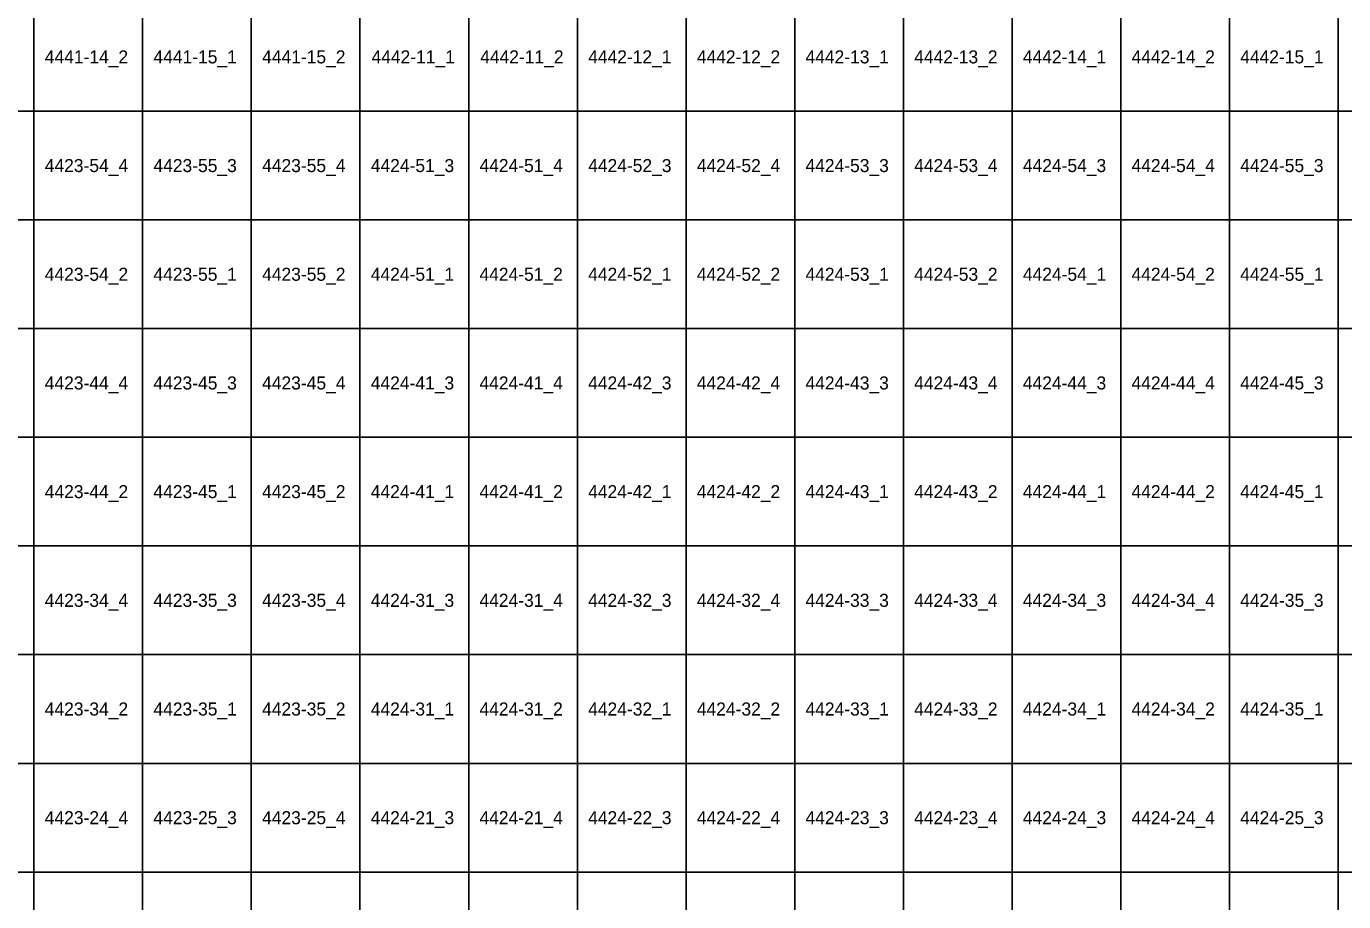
# Model space of a CAD drawing. Extents: x 312500 to 765000, y 172500 to 440000.
# Drawn here: x 667325 to 697629, y 331819 to 351952 of the extents above; entities that cross this region are included whole.
import ezdxf

# ---------------------------------------------------------------- set-up
doc = ezdxf.new("R2010")
doc.units = 0
doc.layers.add('Topo5_ramis_TKS2025', color=7, linetype='Continuous')
doc.layers.add('Topo5_ramis_TKS2025_Nr', color=7, linetype='Continuous')

msp = doc.modelspace()

# ---------------------------------------------------------------- linework, layer by layer
at = {"layer": 'Topo5_ramis_TKS2025'}
for points in [[(665000, 350000), (665000, 352500), (667500, 352500), (667500, 350000), (665000, 350000)], [(667500, 350000), (667500, 352500), (670000, 352500), (670000, 350000), (667500, 350000)], [(670000, 350000), (670000, 352500), (672500, 352500), (672500, 350000), (670000, 350000)], [(672500, 350000), (672500, 352500), (675000, 352500), (675000, 350000), (672500, 350000)], [(675000, 350000), (675000, 352500), (677500, 352500), (677500, 350000), (675000, 350000)], [(677500, 350000), (677500, 352500), (680000, 352500), (680000, 350000), (677500, 350000)], [(680000, 350000), (680000, 352500), (682500, 352500), (682500, 350000), (680000, 350000)], [(682500, 350000), (682500, 352500), (685000, 352500), (685000, 350000), (682500, 350000)], [(685000, 350000), (685000, 352500), (687500, 352500), (687500, 350000), (685000, 350000)], [(687500, 350000), (687500, 352500), (690000, 352500), (690000, 350000), (687500, 350000)], [(690000, 350000), (690000, 352500), (692500, 352500), (692500, 350000), (690000, 350000)], [(692500, 350000), (692500, 352500), (695000, 352500), (695000, 350000), (692500, 350000)], [(695000, 350000), (695000, 352500), (697500, 352500), (697500, 350000), (695000, 350000)], [(697500, 350000), (697500, 352500), (700000, 352500), (700000, 350000), (697500, 350000)], [(665000, 347500), (665000, 350000), (667500, 350000), (667500, 347500), (665000, 347500)], [(667500, 347500), (667500, 350000), (670000, 350000), (670000, 347500), (667500, 347500)], [(670000, 347500), (670000, 350000), (672500, 350000), (672500, 347500), (670000, 347500)], [(672500, 347500), (672500, 350000), (675000, 350000), (675000, 347500), (672500, 347500)], [(675000, 347500), (675000, 350000), (677500, 350000), (677500, 347500), (675000, 347500)], [(677500, 347500), (677500, 350000), (680000, 350000), (680000, 347500), (677500, 347500)], [(680000, 347500), (680000, 350000), (682500, 350000), (682500, 347500), (680000, 347500)], [(682500, 347500), (682500, 350000), (685000, 350000), (685000, 347500), (682500, 347500)], [(685000, 347500), (685000, 350000), (687500, 350000), (687500, 347500), (685000, 347500)], [(687500, 347500), (687500, 350000), (690000, 350000), (690000, 347500), (687500, 347500)], [(690000, 347500), (690000, 350000), (692500, 350000), (692500, 347500), (690000, 347500)], [(692500, 347500), (692500, 350000), (695000, 350000), (695000, 347500), (692500, 347500)], [(695000, 347500), (695000, 350000), (697500, 350000), (697500, 347500), (695000, 347500)], [(697500, 347500), (697500, 350000), (700000, 350000), (700000, 347500), (697500, 347500)], [(665000, 345000), (665000, 347500), (667500, 347500), (667500, 345000), (665000, 345000)], [(667500, 345000), (667500, 347500), (670000, 347500), (670000, 345000), (667500, 345000)], [(670000, 345000), (670000, 347500), (672500, 347500), (672500, 345000), (670000, 345000)], [(672500, 345000), (672500, 347500), (675000, 347500), (675000, 345000), (672500, 345000)], [(675000, 345000), (675000, 347500), (677500, 347500), (677500, 345000), (675000, 345000)], [(677500, 345000), (677500, 347500), (680000, 347500), (680000, 345000), (677500, 345000)], [(680000, 345000), (680000, 347500), (682500, 347500), (682500, 345000), (680000, 345000)], [(682500, 345000), (682500, 347500), (685000, 347500), (685000, 345000), (682500, 345000)], [(685000, 345000), (685000, 347500), (687500, 347500), (687500, 345000), (685000, 345000)], [(687500, 345000), (687500, 347500), (690000, 347500), (690000, 345000), (687500, 345000)], [(690000, 345000), (690000, 347500), (692500, 347500), (692500, 345000), (690000, 345000)], [(692500, 345000), (692500, 347500), (695000, 347500), (695000, 345000), (692500, 345000)], [(695000, 345000), (695000, 347500), (697500, 347500), (697500, 345000), (695000, 345000)], [(697500, 345000), (697500, 347500), (700000, 347500), (700000, 345000), (697500, 345000)], [(665000, 342500), (665000, 345000), (667500, 345000), (667500, 342500), (665000, 342500)], [(667500, 342500), (667500, 345000), (670000, 345000), (670000, 342500), (667500, 342500)], [(670000, 342500), (670000, 345000), (672500, 345000), (672500, 342500), (670000, 342500)], [(672500, 342500), (672500, 345000), (675000, 345000), (675000, 342500), (672500, 342500)], [(675000, 342500), (675000, 345000), (677500, 345000), (677500, 342500), (675000, 342500)], [(677500, 342500), (677500, 345000), (680000, 345000), (680000, 342500), (677500, 342500)], [(680000, 342500), (680000, 345000), (682500, 345000), (682500, 342500), (680000, 342500)], [(682500, 342500), (682500, 345000), (685000, 345000), (685000, 342500), (682500, 342500)], [(685000, 342500), (685000, 345000), (687500, 345000), (687500, 342500), (685000, 342500)], [(687500, 342500), (687500, 345000), (690000, 345000), (690000, 342500), (687500, 342500)], [(690000, 342500), (690000, 345000), (692500, 345000), (692500, 342500), (690000, 342500)], [(692500, 342500), (692500, 345000), (695000, 345000), (695000, 342500), (692500, 342500)], [(695000, 342500), (695000, 345000), (697500, 345000), (697500, 342500), (695000, 342500)], [(697500, 342500), (697500, 345000), (700000, 345000), (700000, 342500), (697500, 342500)], [(665000, 340000), (665000, 342500), (667500, 342500), (667500, 340000), (665000, 340000)], [(667500, 340000), (667500, 342500), (670000, 342500), (670000, 340000), (667500, 340000)], [(670000, 340000), (670000, 342500), (672500, 342500), (672500, 340000), (670000, 340000)], [(672500, 340000), (672500, 342500), (675000, 342500), (675000, 340000), (672500, 340000)], [(675000, 340000), (675000, 342500), (677500, 342500), (677500, 340000), (675000, 340000)], [(677500, 340000), (677500, 342500), (680000, 342500), (680000, 340000), (677500, 340000)], [(680000, 340000), (680000, 342500), (682500, 342500), (682500, 340000), (680000, 340000)], [(682500, 340000), (682500, 342500), (685000, 342500), (685000, 340000), (682500, 340000)], [(685000, 340000), (685000, 342500), (687500, 342500), (687500, 340000), (685000, 340000)], [(687500, 340000), (687500, 342500), (690000, 342500), (690000, 340000), (687500, 340000)], [(690000, 340000), (690000, 342500), (692500, 342500), (692500, 340000), (690000, 340000)], [(692500, 340000), (692500, 342500), (695000, 342500), (695000, 340000), (692500, 340000)], [(695000, 340000), (695000, 342500), (697500, 342500), (697500, 340000), (695000, 340000)], [(697500, 340000), (697500, 342500), (700000, 342500), (700000, 340000), (697500, 340000)], [(665000, 337500), (665000, 340000), (667500, 340000), (667500, 337500), (665000, 337500)], [(667500, 337500), (667500, 340000), (670000, 340000), (670000, 337500), (667500, 337500)], [(670000, 337500), (670000, 340000), (672500, 340000), (672500, 337500), (670000, 337500)], [(672500, 337500), (672500, 340000), (675000, 340000), (675000, 337500), (672500, 337500)], [(675000, 337500), (675000, 340000), (677500, 340000), (677500, 337500), (675000, 337500)], [(677500, 337500), (677500, 340000), (680000, 340000), (680000, 337500), (677500, 337500)], [(680000, 337500), (680000, 340000), (682500, 340000), (682500, 337500), (680000, 337500)], [(682500, 337500), (682500, 340000), (685000, 340000), (685000, 337500), (682500, 337500)], [(685000, 337500), (685000, 340000), (687500, 340000), (687500, 337500), (685000, 337500)], [(687500, 337500), (687500, 340000), (690000, 340000), (690000, 337500), (687500, 337500)], [(690000, 337500), (690000, 340000), (692500, 340000), (692500, 337500), (690000, 337500)], [(692500, 337500), (692500, 340000), (695000, 340000), (695000, 337500), (692500, 337500)], [(695000, 337500), (695000, 340000), (697500, 340000), (697500, 337500), (695000, 337500)], [(697500, 337500), (697500, 340000), (700000, 340000), (700000, 337500), (697500, 337500)], [(665000, 335000), (665000, 337500), (667500, 337500), (667500, 335000), (665000, 335000)], [(667500, 335000), (667500, 337500), (670000, 337500), (670000, 335000), (667500, 335000)], [(670000, 335000), (670000, 337500), (672500, 337500), (672500, 335000), (670000, 335000)], [(672500, 335000), (672500, 337500), (675000, 337500), (675000, 335000), (672500, 335000)], [(675000, 335000), (675000, 337500), (677500, 337500), (677500, 335000), (675000, 335000)], [(677500, 335000), (677500, 337500), (680000, 337500), (680000, 335000), (677500, 335000)], [(680000, 335000), (680000, 337500), (682500, 337500), (682500, 335000), (680000, 335000)], [(682500, 335000), (682500, 337500), (685000, 337500), (685000, 335000), (682500, 335000)], [(685000, 335000), (685000, 337500), (687500, 337500), (687500, 335000), (685000, 335000)], [(687500, 335000), (687500, 337500), (690000, 337500), (690000, 335000), (687500, 335000)], [(690000, 335000), (690000, 337500), (692500, 337500), (692500, 335000), (690000, 335000)], [(692500, 335000), (692500, 337500), (695000, 337500), (695000, 335000), (692500, 335000)], [(695000, 335000), (695000, 337500), (697500, 337500), (697500, 335000), (695000, 335000)], [(697500, 335000), (697500, 337500), (700000, 337500), (700000, 335000), (697500, 335000)], [(665000, 332500), (665000, 335000), (667500, 335000), (667500, 332500), (665000, 332500)], [(667500, 332500), (667500, 335000), (670000, 335000), (670000, 332500), (667500, 332500)], [(670000, 332500), (670000, 335000), (672500, 335000), (672500, 332500), (670000, 332500)], [(672500, 332500), (672500, 335000), (675000, 335000), (675000, 332500), (672500, 332500)], [(675000, 332500), (675000, 335000), (677500, 335000), (677500, 332500), (675000, 332500)], [(677500, 332500), (677500, 335000), (680000, 335000), (680000, 332500), (677500, 332500)], [(680000, 332500), (680000, 335000), (682500, 335000), (682500, 332500), (680000, 332500)], [(682500, 332500), (682500, 335000), (685000, 335000), (685000, 332500), (682500, 332500)], [(685000, 332500), (685000, 335000), (687500, 335000), (687500, 332500), (685000, 332500)], [(687500, 332500), (687500, 335000), (690000, 335000), (690000, 332500), (687500, 332500)], [(690000, 332500), (690000, 335000), (692500, 335000), (692500, 332500), (690000, 332500)], [(692500, 332500), (692500, 335000), (695000, 335000), (695000, 332500), (692500, 332500)], [(695000, 332500), (695000, 335000), (697500, 335000), (697500, 332500), (695000, 332500)], [(697500, 332500), (697500, 335000), (700000, 335000), (700000, 332500), (697500, 332500)], [(665000, 330000), (665000, 332500), (667500, 332500), (667500, 330000), (665000, 330000)], [(667500, 330000), (667500, 332500), (670000, 332500), (670000, 330000), (667500, 330000)], [(670000, 330000), (670000, 332500), (672500, 332500), (672500, 330000), (670000, 330000)], [(672500, 330000), (672500, 332500), (675000, 332500), (675000, 330000), (672500, 330000)], [(675000, 330000), (675000, 332500), (677500, 332500), (677500, 330000), (675000, 330000)], [(677500, 330000), (677500, 332500), (680000, 332500), (680000, 330000), (677500, 330000)], [(680000, 330000), (680000, 332500), (682500, 332500), (682500, 330000), (680000, 330000)], [(682500, 330000), (682500, 332500), (685000, 332500), (685000, 330000), (682500, 330000)], [(685000, 330000), (685000, 332500), (687500, 332500), (687500, 330000), (685000, 330000)], [(687500, 330000), (687500, 332500), (690000, 332500), (690000, 330000), (687500, 330000)], [(690000, 330000), (690000, 332500), (692500, 332500), (692500, 330000), (690000, 330000)], [(692500, 330000), (692500, 332500), (695000, 332500), (695000, 330000), (692500, 330000)], [(695000, 330000), (695000, 332500), (697500, 332500), (697500, 330000), (695000, 330000)], [(697500, 330000), (697500, 332500), (700000, 332500), (700000, 330000), (697500, 330000)]]:
    msp.add_lwpolyline(points, dxfattribs=at)

# ---------------------------------------------------------------- texts
at = {"layer": 'Topo5_ramis_TKS2025_Nr'}
for s, p in [('4441-14_2', (667748, 351100)), ('4441-15_1', (670248, 351100)), ('4441-15_2', (672748, 351100)), ('4442-11_1', (675264, 351100)), ('4442-11_2', (677764, 351100)), ('4442-12_1', (680248, 351100)), ('4442-12_2', (682748, 351100)), ('4442-13_1', (685248, 351100)), ('4442-13_2', (687748, 351100)), ('4442-14_1', (690248, 351100)), ('4442-14_2', (692748, 351100)), ('4442-15_1', (695248, 351100)), ('4423-54_4', (667748, 348600)), ('4423-55_3', (670248, 348600)), ('4423-55_4', (672748, 348600)), ('4424-51_3', (675248, 348600)), ('4424-51_4', (677748, 348600)), ('4424-52_3', (680248, 348600)), ('4424-52_4', (682748, 348600)), ('4424-53_3', (685248, 348600)), ('4424-53_4', (687748, 348600)), ('4424-54_3', (690248, 348600)), ('4424-54_4', (692748, 348600)), ('4424-55_3', (695248, 348600)), ('4423-54_2', (667748, 346100)), ('4423-55_1', (670248, 346100)), ('4423-55_2', (672748, 346100)), ('4424-51_1', (675248, 346100)), ('4424-51_2', (677748, 346100)), ('4424-52_1', (680248, 346100)), ('4424-52_2', (682748, 346100)), ('4424-53_1', (685248, 346100)), ('4424-53_2', (687748, 346100)), ('4424-54_1', (690248, 346100)), ('4424-54_2', (692748, 346100)), ('4424-55_1', (695248, 346100)), ('4423-44_4', (667748, 343600)), ('4423-45_3', (670248, 343600)), ('4423-45_4', (672748, 343600)), ('4424-41_3', (675248, 343600)), ('4424-41_4', (677748, 343600)), ('4424-42_3', (680248, 343600)), ('4424-42_4', (682748, 343600)), ('4424-43_3', (685248, 343600)), ('4424-43_4', (687748, 343600)), ('4424-44_3', (690248, 343600)), ('4424-44_4', (692748, 343600)), ('4424-45_3', (695248, 343600)), ('4423-44_2', (667748, 341100)), ('4423-45_1', (670248, 341100)), ('4423-45_2', (672748, 341100)), ('4424-41_1', (675248, 341100)), ('4424-41_2', (677748, 341100)), ('4424-42_1', (680248, 341100)), ('4424-42_2', (682748, 341100)), ('4424-43_1', (685248, 341100)), ('4424-43_2', (687748, 341100)), ('4424-44_1', (690248, 341100)), ('4424-44_2', (692748, 341100)), ('4424-45_1', (695248, 341100)), ('4423-34_4', (667748, 338600)), ('4423-35_3', (670248, 338600)), ('4423-35_4', (672748, 338600)), ('4424-31_3', (675248, 338600)), ('4424-31_4', (677748, 338600)), ('4424-32_3', (680248, 338600)), ('4424-32_4', (682748, 338600)), ('4424-33_3', (685248, 338600)), ('4424-33_4', (687748, 338600)), ('4424-34_3', (690248, 338600)), ('4424-34_4', (692748, 338600)), ('4424-35_3', (695248, 338600)), ('4423-34_2', (667748, 336100)), ('4423-35_1', (670248, 336100)), ('4423-35_2', (672748, 336100)), ('4424-31_1', (675248, 336100)), ('4424-31_2', (677748, 336100)), ('4424-32_1', (680248, 336100)), ('4424-32_2', (682748, 336100)), ('4424-33_1', (685248, 336100)), ('4424-33_2', (687748, 336100)), ('4424-34_1', (690248, 336100)), ('4424-34_2', (692748, 336100)), ('4424-35_1', (695248, 336100)), ('4423-24_4', (667748, 333600)), ('4423-25_3', (670248, 333600)), ('4423-25_4', (672748, 333600)), ('4424-21_3', (675248, 333600)), ('4424-21_4', (677748, 333600)), ('4424-22_3', (680248, 333600)), ('4424-22_4', (682748, 333600)), ('4424-23_3', (685248, 333600)), ('4424-23_4', (687748, 333600)), ('4424-24_3', (690248, 333600)), ('4424-24_4', (692748, 333600)), ('4424-25_3', (695248, 333600))]:
    msp.add_text(s, height=300, dxfattribs=at).set_placement(p)

doc.saveas('drawing.dxf')
